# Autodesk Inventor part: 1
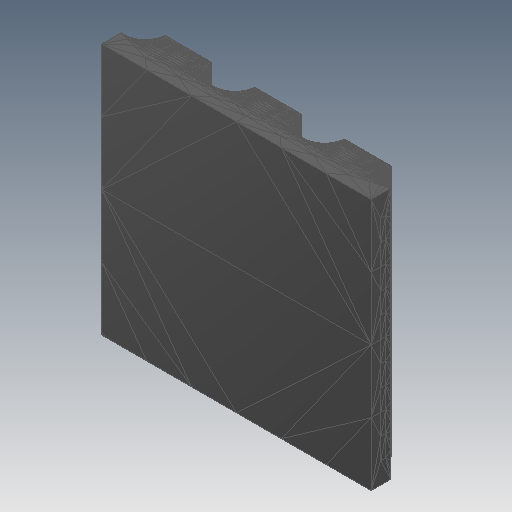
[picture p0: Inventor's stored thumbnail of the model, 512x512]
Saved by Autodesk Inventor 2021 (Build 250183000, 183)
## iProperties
Created: 2026-04
Part Number: 1
Material: Generic
Document SubType Name: Modeling
Designer: JCBG
Density: 1 g/cm^3
Appearance: Default
Author: JCBG
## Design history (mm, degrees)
node "1"
  node "MeshFeature1"
